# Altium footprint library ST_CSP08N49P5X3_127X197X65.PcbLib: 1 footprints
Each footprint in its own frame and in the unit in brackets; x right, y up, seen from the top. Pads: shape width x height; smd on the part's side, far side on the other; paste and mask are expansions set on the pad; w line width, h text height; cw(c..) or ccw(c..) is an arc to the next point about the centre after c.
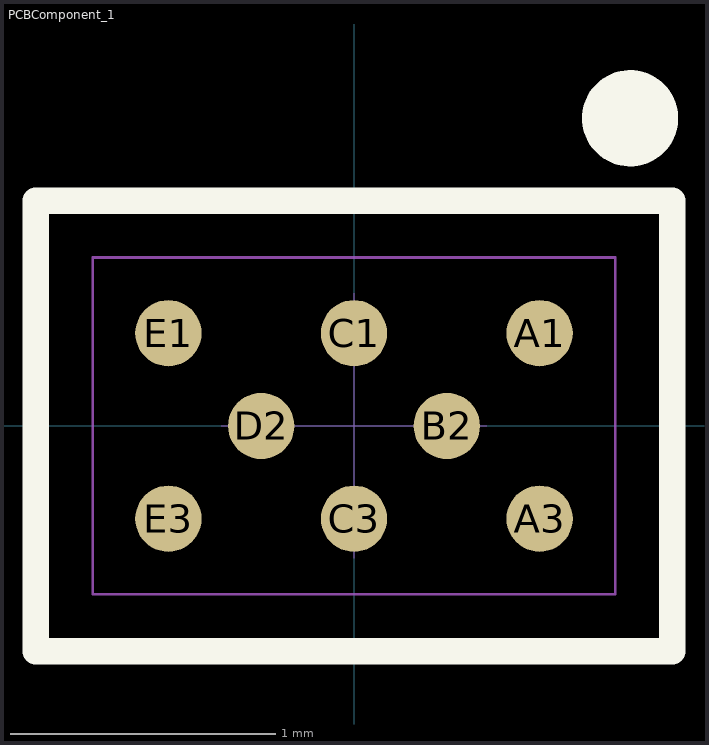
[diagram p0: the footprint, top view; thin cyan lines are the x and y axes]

## PCBComponent_1 [mm]
pads (8):
  round 0.25 smd paste-20 mask+0.045: A1(0.7,0.35) A3(0.7,-0.35) B2(0.35,0) C1(0,0.35) C3(0,-0.35) D2(-0.35,0) E1(-0.7,0.35) E3(-0.7,-0.35)
Top Overlay:
  circle w0.2: c1.041,1.16 r0.081
  lines w0.1: -1.2,-0.85 -1.2,0.85 1.2,0.85 1.2,-0.85 -1.2,-0.85
Top Paste:
  rectangle: 0.535,-0.515 0.865,-0.185
  rectangle: -0.165,-0.515 0.165,-0.185
  rectangle: -0.865,-0.515 -0.535,-0.185
  rectangle: 0.535,0.185 0.865,0.515
  rectangle: 0.185,-0.165 0.515,0.165
  rectangle: -0.165,0.185 0.165,0.515
  rectangle: -0.515,-0.165 -0.185,0.165
  rectangle: -0.865,0.185 -0.535,0.515
Mechanical 15:
  lines w0.001: -0.5,0 0.5,0 ; 0,-0.5 0,0.5
  lines w0.01: -0.985,-0.635 -0.985,0.635 0.985,0.635 0.985,-0.635 -0.985,-0.635
3D body: height 0.63, standoff 0.32, extent -0.985,-0.635 0.985,0.635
